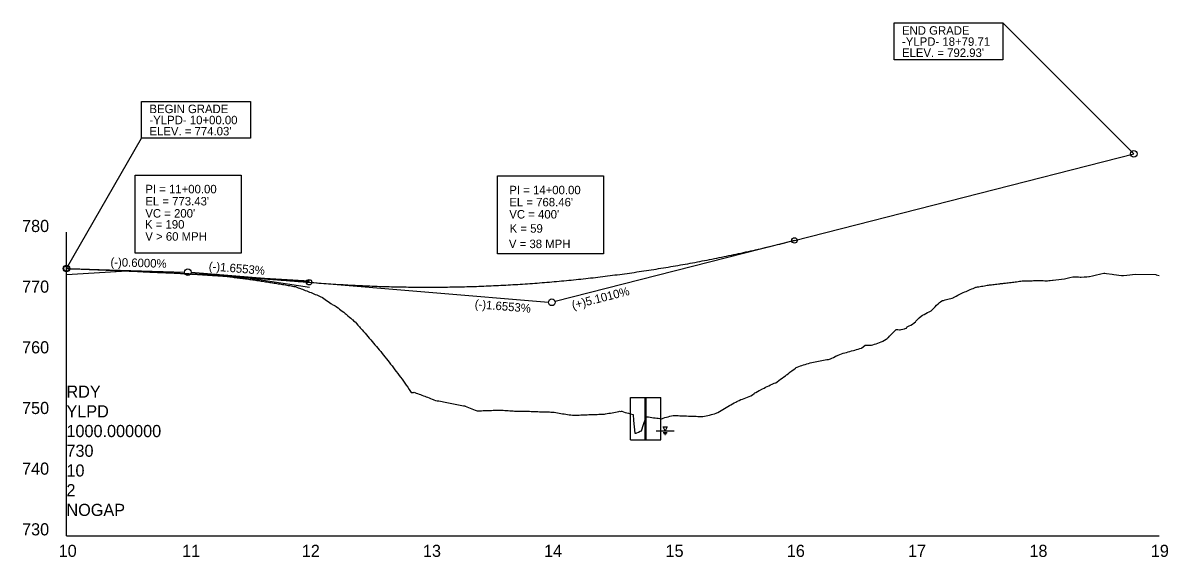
# Model space of a CAD drawing. Extents: x 579185 to 595036, y -53221 to -44640.
# Drawn here: x 579258 to 580202, y -51724 to -51284 of the extents above; entities that cross this region are included whole.
import ezdxf

# ---------------------------------------------------------------- set-up
doc = ezdxf.new("R2010")
doc.units = 0
for name, color, linetype in [('Default', 7, 'Continuous'), ('Exist Profile Cell', 7, 'Continuous'), ('Exist Vertical Profile Ground Line', 7, 'Continuous'), ('Exist Vertical Profile Horizontal Axis Label Major', 7, 'Continuous'), ('Exist Vertical Profile Vertical Axis Label', 7, 'Continuous'), ('Prop Grid Mask', 7, 'Continuous'), ('Prop PFL Text', 7, 'Continuous'), ('Prop Roadway Culvert', 7, 'Continuous'), ('Prop Vertical Profile Curve Label', 7, 'Continuous'), ('Prop Vertical Profile Grade', 7, 'Continuous'), ('Prop Vertical Profile Grade Label', 7, 'Continuous'), ('Prop VPI Label', 7, 'Continuous')]:
    doc.layers.add(name, color=color, linetype=linetype)

msp = doc.modelspace()

# ---------------------------------------------------------------- linework, layer by layer
at = {"layer": 'Default'}
for points in [[(579293.89, -51491.63), (579343.89, -51488.6), (579393.78, -51490.96), (579443.4, -51494.25), (579494.13, -51501.97)], [(579293.89, -51491.63), (579343.89, -51488.6), (579393.78, -51490.96), (579443.4, -51493.74), (579494.13, -51496.65)]]:
    msp.add_lwpolyline(points, dxfattribs=at)
at = {"layer": 'Exist Profile Cell'}
for q in [(579293.89, -51456.78), (580194.35, -51706.78), (579293.89, -51706.78)]:
    msp.add_line((579293.89, -51706.78), q, dxfattribs=at)
at = {"layer": 'Exist Vertical Profile Ground Line'}
for points in [[(579293.89, -51486.63), (579303.27, -51486.97), (579307.95, -51487.13), (579312.64, -51487.3), (579317.48, -51487.48), (579318.39, -51487.51), (579319.67, -51487.56), (579322.02, -51487.67), (579324.36, -51487.77), (579326.7, -51487.87), (579329.05, -51487.98), (579331.39, -51488.08), (579333.74, -51488.19), (579336.08, -51488.29), (579338.42, -51488.4), (579340.84, -51488.51), (579343.4, -51488.61), (579345.45, -51488.7), (579347.8, -51488.81), (579350.14, -51488.92), (579352.49, -51489.03), (579354.83, -51489.14), (579357.17, -51489.25), (579359.52, -51489.36), (579361.86, -51489.47), (579362.51, -51489.5), (579364.2, -51489.56), (579366.55, -51489.66), (579368.42, -51489.73), (579368.89, -51489.75), (579371.24, -51489.85), (579373.58, -51489.95), (579375.92, -51490.05), (579378.27, -51490.15), (579380.61, -51490.26), (579382.95, -51490.36), (579385.3, -51490.44), (579387.64, -51490.53), (579389.99, -51490.62), (579392.33, -51490.71), (579393.57, -51490.76), (579394.67, -51490.8), (579395.84, -51490.85), (579397.02, -51490.89), (579398.19, -51490.94), (579399.36, -51490.99), (579400.53, -51491.03), (579401.7, -51491.08), (579402.88, -51491.13), (579404.05, -51491.17), (579405.22, -51491.22), (579406.39, -51491.27), (579407.56, -51491.31), (579408.74, -51491.36), (579409.91, -51491.41), (579411.08, -51491.45), (579411.75, -51491.48), (579412.25, -51491.53), (579413.42, -51491.65), (579414.59, -51491.76), (579415.77, -51491.88), (579416.94, -51492), (579417.43, -51492.05), (579417.76, -51492.09), (579418.11, -51492.13), (579419.28, -51492.27), (579420.45, -51492.4), (579421.63, -51492.54), (579422.8, -51492.69), (579423.97, -51492.83), (579425.14, -51492.97), (579426.31, -51493.12), (579427.49, -51493.27), (579428.66, -51493.42), (579429.83, -51493.57), (579431, -51493.72), (579432.17, -51493.88), (579433.34, -51494.03), (579434.52, -51494.19), (579435.69, -51494.35), (579436.86, -51494.51), (579437.17, -51494.55), (579438.03, -51494.66), (579439.2, -51494.8), (579440.38, -51494.95), (579441.55, -51495.09), (579442.72, -51495.24), (579443.89, -51495.39), (579445.06, -51495.55), (579446.24, -51495.7), (579447.41, -51495.86), (579448.61, -51496.03), (579449.75, -51496.2), (579450.92, -51496.37), (579452.09, -51496.55), (579453.27, -51496.73), (579454.44, -51496.91), (579455.61, -51497.09), (579456.78, -51497.28), (579457.95, -51497.46), (579459.13, -51497.65)], [(580045.78, -51501.65), (580046.94, -51501.44), (580048.09, -51501.23), (580049.25, -51501.02), (580050.41, -51500.81), (580051.56, -51500.6), (580052.72, -51500.4), (580053.87, -51500.19), (580054.59, -51500.07), (580055.03, -51500.04), (580056.19, -51499.96), (580057.34, -51499.88), (580058.5, -51499.73), (580059.66, -51499.58), (580060.81, -51499.43), (580061.97, -51499.29), (580063.12, -51499.14), (580063.64, -51499.08), (580064.28, -51499.02), (580065.52, -51498.91), (580066.59, -51498.8), (580067.75, -51498.68), (580068.91, -51498.53), (580070.06, -51498.37), (580071.22, -51498.22), (580072.37, -51498.07), (580073.53, -51497.92), (580074.69, -51497.77), (580075.84, -51497.62), (580077, -51497.48), (580078.36, -51497.31), (580079.31, -51497.14), (580080.47, -51496.94), (580081.62, -51496.78), (580082.78, -51496.8), (580083.94, -51496.81), (580085.09, -51496.83), (580086.25, -51496.85), (580086.87, -51496.86), (580087.41, -51496.82), (580088.56, -51496.74), (580089.72, -51496.65), (580090.87, -51496.57), (580092.03, -51496.49), (580092.36, -51496.47), (580093.19, -51496.48), (580094.34, -51496.51), (580095.5, -51496.53), (580096.66, -51496.55), (580097.81, -51496.58), (580098.97, -51496.6), (580100.12, -51496.62), (580101.28, -51496.64), (580102.44, -51496.62), (580103.59, -51496.59), (580104.4, -51496.57), (580104.75, -51496.53), (580106.57, -51496.33), (580107.06, -51496.27), (580109.37, -51495.96), (580111.69, -51495.65), (580114, -51495.34), (580116.48, -51495.01), (580118.62, -51494.53), (580120.94, -51494), (580123.25, -51493.48), (580123.98, -51493.32), (580125.56, -51493.42), (580127.87, -51493.59), (580129.4, -51493.7), (580130.19, -51493.63), (580132.71, -51493.44), (580134.81, -51493.36), (580136.48, -51493.3), (580137.12, -51493.16), (580139.44, -51492.64), (580141.75, -51492.13), (580146.37, -51491.1), (580148.77, -51490.51), (580149.67, -51490.55), (580151, -51490.71), (580155.62, -51491.26), (580157.07, -51491.44), (580163.46, -51492.44), (580164.99, -51492.47), (580167.75, -51492.2), (580174.84, -51491.26), (580191.62, -51491.61), (580192.02, -51491.72), (580194.35, -51492.4)], [(579459.13, -51497.65), (579460.3, -51497.84), (579461.53, -51498.04), (579462.64, -51498.21), (579463.81, -51498.39), (579464.99, -51498.57), (579466.16, -51498.75), (579467.33, -51498.93), (579468.5, -51499.12), (579469.67, -51499.31), (579470.84, -51499.5), (579472.02, -51499.69), (579473.19, -51499.88), (579474.36, -51500.08), (579475.53, -51500.27), (579476.7, -51500.47), (579477.88, -51500.67), (579479.05, -51500.87), (579480.22, -51501.08), (579481.39, -51501.29), (579482.56, -51501.51), (579483.74, -51501.95), (579484.91, -51502.39), (579486.08, -51502.84), (579486.79, -51503.14), (579487.25, -51503.3), (579488.57, -51503.75), (579489.59, -51504.15), (579490.77, -51504.6), (579491.94, -51505.05), (579493.11, -51505.51), (579494.28, -51505.98), (579495.45, -51506.45), (579496.63, -51506.93), (579497.8, -51507.41), (579498.97, -51507.89), (579500.14, -51508.38), (579501.31, -51508.88), (579502.49, -51509.38), (579503.66, -51509.88), (579504.42, -51510.21), (579504.83, -51510.49), (579506, -51511.29), (579507.17, -51512.1), (579508.34, -51512.92), (579509.52, -51513.74), (579510.69, -51514.58), (579511.86, -51515.42), (579512.31, -51515.75), (579513.03, -51516.15), (579514.2, -51516.81), (579515.38, -51517.49), (579516.08, -51517.9), (579516.55, -51518.24), (579517.72, -51519.1), (579518.89, -51519.97), (579520.06, -51520.85), (579521.24, -51521.73), (579522.41, -51522.63), (579523.58, -51523.59), (579524.37, -51524.23), (579524.75, -51524.55), (579525.92, -51525.55), (579527.09, -51526.57), (579528.27, -51527.59), (579529.44, -51528.61), (579529.89, -51529.01), (579530.61, -51529.62), (579531.78, -51530.61), (579532.15, -51530.93), (579532.95, -51531.85), (579534.13, -51533.2), (579535.3, -51534.56), (579536.08, -51535.47), (579536.47, -51535.9), (579537.64, -51537.21), (579538.81, -51538.52), (579539.99, -51539.85), (579541.16, -51541.19), (579542.33, -51542.53), (579543.5, -51543.89), (579544.67, -51545.25), (579545.84, -51546.63), (579547.02, -51548.01), (579548.19, -51549.4), (579549.36, -51550.81), (579550.53, -51552.22), (579551.7, -51553.65), (579552.88, -51555.08), (579554.05, -51556.52), (579555.22, -51557.98), (579556.39, -51559.44), (579557.56, -51560.92), (579558.74, -51562.4), (579559.91, -51563.89), (579561.08, -51565.4), (579562.25, -51566.91), (579563.42, -51568.44), (579564.59, -51569.97), (579565.77, -51571.52), (579566.94, -51573.07)], [(579935.49, -51556.09), (579936.85, -51555.68), (579938.22, -51555.28), (579939.58, -51554.88), (579940.94, -51554.49), (579942.49, -51554.04), (579943.66, -51553.77), (579945.02, -51553.45), (579946.38, -51553.11), (579947.74, -51552.63), (579949.1, -51552.15), (579949.49, -51552.02), (579950.46, -51551.27), (579952.26, -51549.88), (579953.3, -51549.84), (579954.55, -51549.81), (579955.91, -51549.79), (579957.27, -51549.72), (579958.63, -51549.37), (579959.99, -51549.01), (579961.35, -51548.61), (579962.71, -51548.09), (579964.07, -51547.56), (579965.43, -51547.03), (579966.07, -51546.77), (579966.8, -51546.36), (579968.16, -51545.58), (579969.52, -51544.8), (579970.26, -51544.38), (579970.88, -51543.77), (579971.27, -51543.38), (579972.24, -51542.41), (579973.6, -51541.04), (579974.96, -51539.66), (579975.57, -51539.05), (579976.32, -51538.2), (579977.05, -51537.39), (579977.74, -51536.81), (579979.04, -51536.94), (579980.4, -51537.08), (579981.15, -51537.14), (579981.77, -51536.98), (579983.13, -51536.63), (579984.49, -51536.29), (579985.19, -51536.11), (579985.85, -51535.87), (579986.23, -51535.74), (579986.8, -51534.64), (579987.21, -51534.44), (579988.57, -51533.82), (579989.93, -51533.2), (579991.29, -51532.57), (579992.65, -51531.33), (579993.61, -51530.47), (579994.01, -51530.06), (579995.38, -51528.69), (579996.74, -51527.33), (579998.31, -51525.76), (579999.46, -51525.14), (580000.82, -51524.41), (580002.18, -51523.68), (580003.54, -51522.96), (580004.9, -51522.24), (580006.5, -51521.4), (580007.62, -51520.31), (580008.78, -51519.19), (580009.94, -51518.06), (580011.09, -51516.94), (580012.25, -51515.83), (580013.41, -51514.71), (580014.2, -51513.95), (580014.56, -51513.77), (580015.99, -51513.08), (580016.87, -51512.84), (580018.03, -51512.53), (580019.19, -51512.22), (580020.34, -51511.91), (580021.5, -51511.61), (580022.66, -51511.3), (580023.81, -51511), (580024.62, -51510.79), (580024.97, -51510.59), (580026.12, -51509.95), (580027.28, -51509.31), (580028.44, -51508.68), (580029.59, -51508.05), (580030.75, -51507.43), (580031.91, -51506.93), (580033.06, -51506.42), (580034.22, -51505.92), (580035.37, -51505.42), (580036.53, -51504.92), (580037.69, -51504.43), (580038.84, -51503.94), (580040, -51503.45), (580041.16, -51502.96), (580042.31, -51502.48), (580043.47, -51502), (580043.85, -51501.84), (580044.62, -51501.76), (580045.78, -51501.65)], [(579810.38, -51608.31), (579811.65, -51608.36), (579813.01, -51608.41), (579814.37, -51608.47), (579815.73, -51608.53), (579817.09, -51608.58), (579818.45, -51608.57), (579819.81, -51608.27), (579821.17, -51607.96), (579822.53, -51607.65), (579823.89, -51607.35), (579825.5, -51606.98), (579826.62, -51606.65), (579827.98, -51606.24), (579829.34, -51605.84), (579830, -51605.64), (579830.7, -51605.22), (579832.06, -51604.42), (579833.42, -51603.61), (579834.78, -51602.81), (579836.14, -51602), (579837.5, -51601.19), (579839.12, -51600.22), (579840.23, -51599.62), (579841.59, -51598.87), (579842.95, -51598.12), (579844.31, -51597.37), (579845.67, -51596.62), (579846.4, -51596.22), (579847.03, -51595.93), (579848.39, -51595.29), (579849.75, -51594.67), (579851.11, -51594.15), (579852.47, -51593.62), (579853.84, -51593.1), (579855.2, -51592.57), (579856.56, -51592.05), (579858.08, -51591.46), (579859.28, -51590.6), (579860.64, -51589.63), (579861.27, -51589.18), (579862, -51588.76), (579863.36, -51587.99), (579864.72, -51587.22), (579866.08, -51586.45), (579866.41, -51586.27), (579867.44, -51585.78), (579868.81, -51585.14), (579870.17, -51584.49), (579871.53, -51583.85), (579872.89, -51583.21), (579874.25, -51582.57), (579875.61, -51581.93), (579877.24, -51581.16), (579878.55, -51580.78), (579879.69, -51579.94), (579881.05, -51578.93), (579882.42, -51577.92), (579883.78, -51576.92), (579885.14, -51575.92), (579886.5, -51574.91), (579887.32, -51574.31), (579887.86, -51573.95), (579889.22, -51572.88), (579890.12, -51572.16), (579890.58, -51571.81), (579891.94, -51570.77), (579893.3, -51569.73), (579894.66, -51568.69), (579895.32, -51568.19), (579896.03, -51567.86), (579897.42, -51567.22), (579898.75, -51566.81), (579900.11, -51566.4), (579901.47, -51565.98), (579902.83, -51565.57), (579904.19, -51565.16), (579905.55, -51564.76), (579906.91, -51564.46), (579908.27, -51564.16), (579909.63, -51563.87), (579911, -51563.59), (579912.36, -51563.32), (579913.72, -51563.04), (579915.08, -51562.77), (579916.44, -51562.5), (579917.8, -51562.23), (579919.16, -51561.97), (579920.52, -51561.7), (579921.88, -51561.45), (579923.52, -51561.14), (579924.61, -51560.57), (579925.97, -51559.86), (579927.33, -51559.15), (579928.21, -51558.69), (579928.69, -51558.51), (579930.05, -51558), (579931.41, -51557.49), (579932.77, -51556.98), (579934.13, -51556.49), (579935.49, -51556.09)], [(579566.94, -51573.07), (579568.11, -51574.64), (579569.28, -51576.21), (579570.45, -51577.8), (579571.63, -51579.39), (579572.23, -51580.22), (579572.8, -51581.05), (579573.97, -51582.77), (579575.14, -51584.5), (579576.31, -51586.24), (579577.49, -51588), (579578.01, -51588.8), (579578.66, -51588.75), (579579.83, -51588.65), (579580.53, -51588.6), (579581, -51588.78), (579582.17, -51589.24), (579583.34, -51589.67), (579584.52, -51590.11), (579585.69, -51590.54), (579586.86, -51590.98), (579588.03, -51591.42), (579589.2, -51591.86), (579590.38, -51592.31), (579591.55, -51592.75), (579592.72, -51593.2), (579593.89, -51593.66), (579595.25, -51594.18), (579596.09, -51594.51), (579596.61, -51594.69), (579598.16, -51595.29), (579599.34, -51595.51), (579600.7, -51595.77), (579602.06, -51596.03), (579603.42, -51596.29), (579604.78, -51596.55), (579606.14, -51596.81), (579607.5, -51597.07), (579608.86, -51597.33), (579610.22, -51597.59), (579611.58, -51597.85), (579612.94, -51598.1), (579614.31, -51598.36), (579615.67, -51598.62), (579617.03, -51598.88), (579618.39, -51599.14), (579619.75, -51599.4), (579621.11, -51599.66), (579622.16, -51599.85), (579622.47, -51599.98), (579623.83, -51600.53), (579625.19, -51601.07), (579626.55, -51601.61), (579627.92, -51602.15), (579629.28, -51602.7), (579630.64, -51603.24), (579632.41, -51603.9), (579632.89, -51603.89), (579633.36, -51603.88), (579634.72, -51603.83), (579636.08, -51603.78), (579637.44, -51603.73), (579638.8, -51603.68), (579640.16, -51603.63), (579641.53, -51603.58), (579642.89, -51603.53), (579644.25, -51603.48), (579645.61, -51603.43), (579646.97, -51603.38), (579648.33, -51603.33), (579649.69, -51603.28), (579651.05, -51603.23), (579651.4, -51603.22), (579652.41, -51603.3), (579653.77, -51603.4), (579655.13, -51603.5), (579656.5, -51603.6), (579657.86, -51603.7), (579659.22, -51603.8), (579660.58, -51603.9), (579661.94, -51603.99), (579663.3, -51604.09), (579664.66, -51604.18), (579665.22, -51604.22), (579666.02, -51604.21), (579667.38, -51604.2), (579668.74, -51604.19), (579670.11, -51604.18), (579671.47, -51604.17), (579672.83, -51604.17), (579674.19, -51604.22), (579675.55, -51604.28), (579676.91, -51604.33), (579678.27, -51604.38), (579679.63, -51604.44), (579680.99, -51604.49), (579682.35, -51604.54), (579683.71, -51604.59), (579685.08, -51604.63), (579686.44, -51604.68), (579687.8, -51604.73)], [(579687.8, -51604.73), (579689.16, -51604.77), (579689.94, -51604.8), (579690.52, -51604.81), (579691.88, -51604.84), (579693.24, -51604.87), (579694.7, -51604.9), (579695.96, -51605.11), (579697.32, -51605.34), (579698.69, -51605.56), (579700.05, -51605.79), (579701.41, -51606.01), (579702.77, -51606.23), (579704.13, -51606.45), (579705.49, -51606.67), (579706.85, -51606.89), (579708.21, -51607.11), (579709.57, -51607.32), (579710.93, -51607.54), (579712.3, -51607.49), (579713.66, -51607.44), (579715.02, -51607.39), (579716.38, -51607.35), (579717.74, -51607.3), (579718.59, -51607.27), (579719.1, -51607.25), (579720.46, -51607.2), (579721.82, -51607.14), (579723.18, -51607.09), (579724.54, -51607.04), (579725.9, -51606.99), (579727.27, -51606.94), (579728.63, -51606.89), (579729.99, -51606.84), (579731.35, -51606.79), (579732.71, -51606.74), (579734.07, -51606.69), (579735.43, -51606.64), (579736.79, -51606.59), (579737.47, -51606.57), (579738.15, -51606.44), (579739.51, -51606.19), (579740.88, -51605.94), (579742.24, -51605.69), (579743.6, -51605.44), (579744.96, -51605.19), (579746.32, -51604.93), (579747.68, -51604.68), (579749.04, -51604.43), (579749.75, -51604.3), (579750.64, -51604.47), (579751.38, -51604.09), (579751.76, -51604.24), (579753.12, -51604.76), (579754.48, -51605.13), (579755.85, -51605.51), (579757.21, -51605.88), (579758.57, -51606.25), (579759.93, -51606.61), (579760.99, -51606.9), (579761.29, -51611.75), (579762.46, -51622.22), (579763.51, -51622.25), (579764.01, -51622.02), (579765.37, -51621.4), (579766.73, -51620.78), (579767.82, -51620.28), (579769.46, -51615.28), (579771.03, -51610.48), (579771.24, -51608.63), (579772.18, -51608.77), (579773.54, -51608.97), (579774.9, -51609.18), (579776.26, -51609.38), (579777.62, -51609.58), (579778.59, -51609.73), (579778.98, -51609.77), (579780.34, -51609.92), (579781.7, -51610.06), (579783.07, -51610.21), (579784.51, -51610.36), (579785.79, -51609.95), (579787.15, -51609.51), (579788.51, -51609.15), (579789.87, -51608.79), (579791.23, -51608.42), (579792.59, -51608.06), (579793.95, -51607.71), (579795.31, -51607.75), (579796.67, -51607.8), (579798.04, -51607.84), (579799.4, -51607.88), (579800.76, -51607.92), (579801.58, -51607.94), (579802.12, -51607.97), (579803.48, -51608.03), (579804.84, -51608.09), (579806.47, -51608.16), (579807.76, -51608.17), (579808.92, -51608.23), (579810.38, -51608.31)]]:
    msp.add_lwpolyline(points, dxfattribs=at)
at = {"layer": 'Prop Grid Mask'}
for points in [[(579975.96, -51284.19), (580065.7, -51284.19), (580065.7, -51314.59), (579975.96, -51314.59)], [(579355.73, -51348.84), (579445.48, -51348.84), (579445.48, -51379.24), (579355.73, -51379.24)], [(579350.5, -51409.65), (579437.86, -51409.65), (579437.86, -51473.83), (579350.5, -51473.83)], [(579649.07, -51410.3), (579736.43, -51410.3), (579736.43, -51474.48), (579649.07, -51474.48)]]:
    msp.add_lwpolyline(points, close=True, dxfattribs=at)
at = {"layer": 'Prop PFL Text'}
for p, q in [((579779.86, -51620.33), (579794.86, -51620.33)), ((579785.56, -51621.85), (579789.06, -51621.85)), ((579786.26, -51622.6), (579788.36, -51622.6)), ((579786.96, -51623.35), (579787.66, -51623.35))]:
    msp.add_line(p, q, dxfattribs=at)
msp.add_lwpolyline([(579785.61, -51617.08), (579789.11, -51617.08), (579787.36, -51620.33)], close=True, dxfattribs=at)
at = {"layer": 'Prop Roadway Culvert'}
for p, q in [((579758.79, -51627.83), (579758.79, -51592.83)), ((579758.79, -51592.83), (579783.79, -51592.83)), ((579770.79, -51627.83), (579770.79, -51592.83)), ((579771.79, -51627.83), (579771.79, -51592.83)), ((579783.79, -51627.83), (579783.79, -51592.83)), ((579758.79, -51627.83), (579783.79, -51627.83))]:
    msp.add_line(p, q, dxfattribs=at)
at = {"layer": 'Prop Vertical Profile Curve Label'}
for p, q in [((580173.6, -51392.11), (580065.7, -51284.19)), ((579293.89, -51486.63), (579355.73, -51379.24))]:
    msp.add_line(p, q, dxfattribs=at)
for centre in [(579893.89, -51463.45), (579293.89, -51486.63), (579493.89, -51497.91), (579493.89, -51497.91)]:
    msp.add_circle(centre, 2.25, dxfattribs=at)
at = {"layer": 'Prop Vertical Profile Grade'}
msp.add_line((579893.89, -51463.45), (580173.6, -51392.11), dxfattribs=at)
for points in [[(579493.89, -51497.91), (579501.89, -51498.54), (579509.89, -51499.13), (579517.89, -51499.65), (579525.89, -51500.13), (579533.89, -51500.54), (579541.89, -51500.91), (579549.89, -51501.22), (579557.89, -51501.48), (579565.89, -51501.68), (579573.89, -51501.83), (579581.89, -51501.92), (579589.89, -51501.96), (579597.89, -51501.95), (579605.89, -51501.88), (579613.89, -51501.76), (579621.89, -51501.59), (579629.89, -51501.36), (579637.89, -51501.07), (579645.89, -51500.73), (579653.89, -51500.34), (579661.89, -51499.9), (579669.89, -51499.4), (579677.89, -51498.84), (579685.89, -51498.23), (579693.89, -51497.57), (579701.89, -51496.86), (579709.89, -51496.09), (579717.89, -51495.26), (579725.89, -51494.38), (579733.89, -51493.45), (579741.89, -51492.46), (579749.89, -51491.42), (579757.89, -51490.33), (579765.89, -51489.18), (579773.89, -51487.98), (579781.89, -51486.72), (579789.89, -51485.41), (579797.89, -51484.05), (579805.89, -51482.63), (579813.89, -51481.15), (579821.89, -51479.63), (579829.89, -51478.05), (579837.89, -51476.41), (579845.89, -51474.72), (579853.89, -51472.98), (579861.89, -51471.18), (579869.89, -51469.33), (579877.89, -51467.43), (579885.89, -51465.47), (579893.89, -51463.45)], [(579293.89, -51486.63), (579297.89, -51486.76), (579301.89, -51486.88), (579305.89, -51487.01), (579309.89, -51487.15), (579313.89, -51487.29), (579317.89, -51487.43), (579321.89, -51487.58), (579325.89, -51487.73), (579329.89, -51487.88), (579333.89, -51488.04), (579337.89, -51488.21), (579341.89, -51488.38), (579345.89, -51488.55), (579349.89, -51488.73), (579353.89, -51488.91), (579357.89, -51489.09), (579361.89, -51489.28), (579365.89, -51489.48), (579369.89, -51489.67), (579373.89, -51489.88), (579377.89, -51490.08), (579381.89, -51490.29), (579385.89, -51490.51), (579389.89, -51490.73), (579393.89, -51490.95), (579397.89, -51491.18), (579401.89, -51491.41), (579405.89, -51491.65), (579409.89, -51491.89), (579413.89, -51492.13), (579417.89, -51492.38), (579421.89, -51492.63), (579425.89, -51492.89), (579429.89, -51493.15), (579433.89, -51493.42), (579437.89, -51493.69), (579441.89, -51493.96), (579445.89, -51494.24), (579449.89, -51494.52), (579453.89, -51494.81), (579457.89, -51495.1), (579461.89, -51495.4), (579465.89, -51495.7), (579469.89, -51496), (579473.89, -51496.31), (579477.89, -51496.62), (579481.89, -51496.94), (579485.89, -51497.26), (579489.89, -51497.58), (579493.89, -51497.91)]]:
    msp.add_spline(points, degree=3, dxfattribs=at)
at = {"layer": 'Prop VPI Label'}
for p, q in [((579893.89, -51463.45), (579696.56, -51513.78)), ((579293.89, -51486.63), (579391.14, -51489.55)), ((579493.89, -51497.91), (579396.63, -51489.86)), ((579493.89, -51497.91), (579691.15, -51514.24))]:
    msp.add_line(p, q, dxfattribs=at)
for centre in [(580173.6, -51392.11), (579293.89, -51486.63), (579393.89, -51489.63), (579693.89, -51514.46)]:
    msp.add_circle(centre, 2.75, dxfattribs=at)

# ---------------------------------------------------------------- texts
at = {"layer": 'Exist Profile Cell'}
for s, p in [('RDY', (579293.89, -51593.03)), ('YLPD', (579293.89, -51609.28)), ('1000.000000', (579293.89, -51625.53)), ('730', (579293.89, -51641.78)), ('10', (579293.89, -51658.03)), ('2', (579293.89, -51674.28)), ('NOGAP', (579293.89, -51690.53))]:
    msp.add_text(s, height=10, dxfattribs=at).set_placement(p)
at = {"layer": 'Exist Vertical Profile Horizontal Axis Label Major'}
for s, p in [('10', (579287.47, -51724.28)), ('11', (579389.31, -51724.28)), ('12', (579487.86, -51724.28)), ('13', (579587.7, -51724.28)), ('14', (579687.54, -51724.28)), ('15', (579787.63, -51724.28)), ('16', (579887.57, -51724.28)), ('17', (579987.43, -51724.28)), ('18', (580087.56, -51724.28)), ('19', (580187.6, -51724.28))]:
    msp.add_text(s, height=10, dxfattribs=at).set_placement(p)
at = {"layer": 'Exist Vertical Profile Vertical Axis Label'}
for s, p in [('780', (579257.32, -51456.53)), ('770', (579257.32, -51506.53)), ('760', (579257.32, -51556.53)), ('750', (579257.32, -51606.53)), ('740', (579257.32, -51656.53)), ('730', (579257.32, -51706.53))]:
    msp.add_text(s, height=10, dxfattribs=at).set_placement(p)
at = {"layer": 'Prop Vertical Profile Curve Label'}
for s, p in [("VC = 200'", (579358.89, -51444.63)), ("VC = 400'", (579658.89, -51445.4)), ('K = 190', (579358.62, -51453.71)), ('V > 60 MPH', (579358.89, -51463.66)), ('K = 59', (579659.17, -51457.09)), ('V = 38 MPH', (579658.56, -51469.8))]:
    msp.add_text(s, height=7, dxfattribs=at).set_placement(p)
at = {"layer": 'Prop Vertical Profile Grade Label'}
for s, rotation, p in [('(-)0.6000%', 358.28164, (579330.08, -51484.72)), ('(-)1.6553%', 355.2686, (579410.99, -51488.04)), ('(+)5.1010%', 14.30824, (579711.34, -51520.33)), ('(-)1.6553%', 355.2686, (579630.19, -51519.22))]:
    msp.add_text(s, height=7, rotation=rotation, dxfattribs=at).set_placement(p)
at = {"layer": 'Prop VPI Label'}
for s, p in [('END GRADE', (579982.52, -51293.91)), ('-YLPD- 18+79.71', (579982.52, -51303.08)), ("ELEV. = 792.93'", (579982.52, -51312.26)), ('BEGIN GRADE', (579362.29, -51358.55)), ('-YLPD- 10+00.00', (579362.29, -51367.73)), ("ELEV. = 774.03'", (579362.29, -51376.91)), ('PI = 11+00.00', (579358.89, -51424.63)), ('PI = 14+00.00', (579658.89, -51425.4)), ("EL = 773.43'", (579358.89, -51434.63)), ("EL = 768.46'", (579658.89, -51435.4))]:
    msp.add_text(s, height=7, dxfattribs=at).set_placement(p)

doc.saveas('drawing.dxf')
